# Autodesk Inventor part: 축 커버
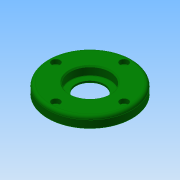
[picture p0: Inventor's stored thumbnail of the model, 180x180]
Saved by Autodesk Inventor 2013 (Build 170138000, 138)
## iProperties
Created: 2015-10
Part Number: 축 커버
Document SubType Name: Modeling
Designer: mdu
Density: 2.71 g/cm^3
Material: 알루미늄 6061
Mass: 110.724 g
Surface Area: 133.807 cm^2
Volume: 40.8575 cm^3
Author: mdu
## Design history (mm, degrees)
sketch "스케치1"
  geometry: C1 r 40 at (0, 0) reference; C2 r 26 at (0, 0) reference; 1 further point
  node "참조1"
  node "참조2"
extrude "돌출1" new body sketch "스케치1" distance "d0" = 10; taper "d1" = 0 deg
extrude "돌출2" join sketch "스케치1" distance "d2" = 3; taper "d3" = 0 deg
hole "구멍1" diameter "d6" = 27; stored, may be unused: countersink angle "d10" = 90 deg, drill point angle "d12" = 118 deg; dims "d7" = 6, "d8" = 38, "d9" = 8.3, "d11" = 8, "d31" = 10, "d32" = 10
sketch "스케치2"
  geometry: C1 r 20 at (0, 0); 1 further point
  constraints: 1 centre point, 1 coincident
  dimensions: "d13" = 40 diameter of C1
extrude "돌출3" cut sketch "스케치2" distance "d14" = 3; taper "d15" = 0 deg
sketch "스케치3"
  geometry: C1 r 1.621 at (0, 32.5) reference; 1 further point
hole "구멍2" sketch "스케치3" at (0, 32.5) diameter "d16" = 4.5; stored, may be unused: countersink angle "d20" = 90 deg, drill point angle "d22" = 118 deg; dims "d17" = 6, "d18" = 8, "d19" = 4.4, "d21" = 8
fillet "모깎기1" dims "d26" = 3, "d27" = 0.3
chamfer "모따기1" distance "d28" = 1; stored, may be unused: second distance "d29" = 2, angle "d30" = 45 deg
node "솔리드1"
pattern_circular "원형 패턴1" dims angle "d24" = 360 deg
node "참조3"
